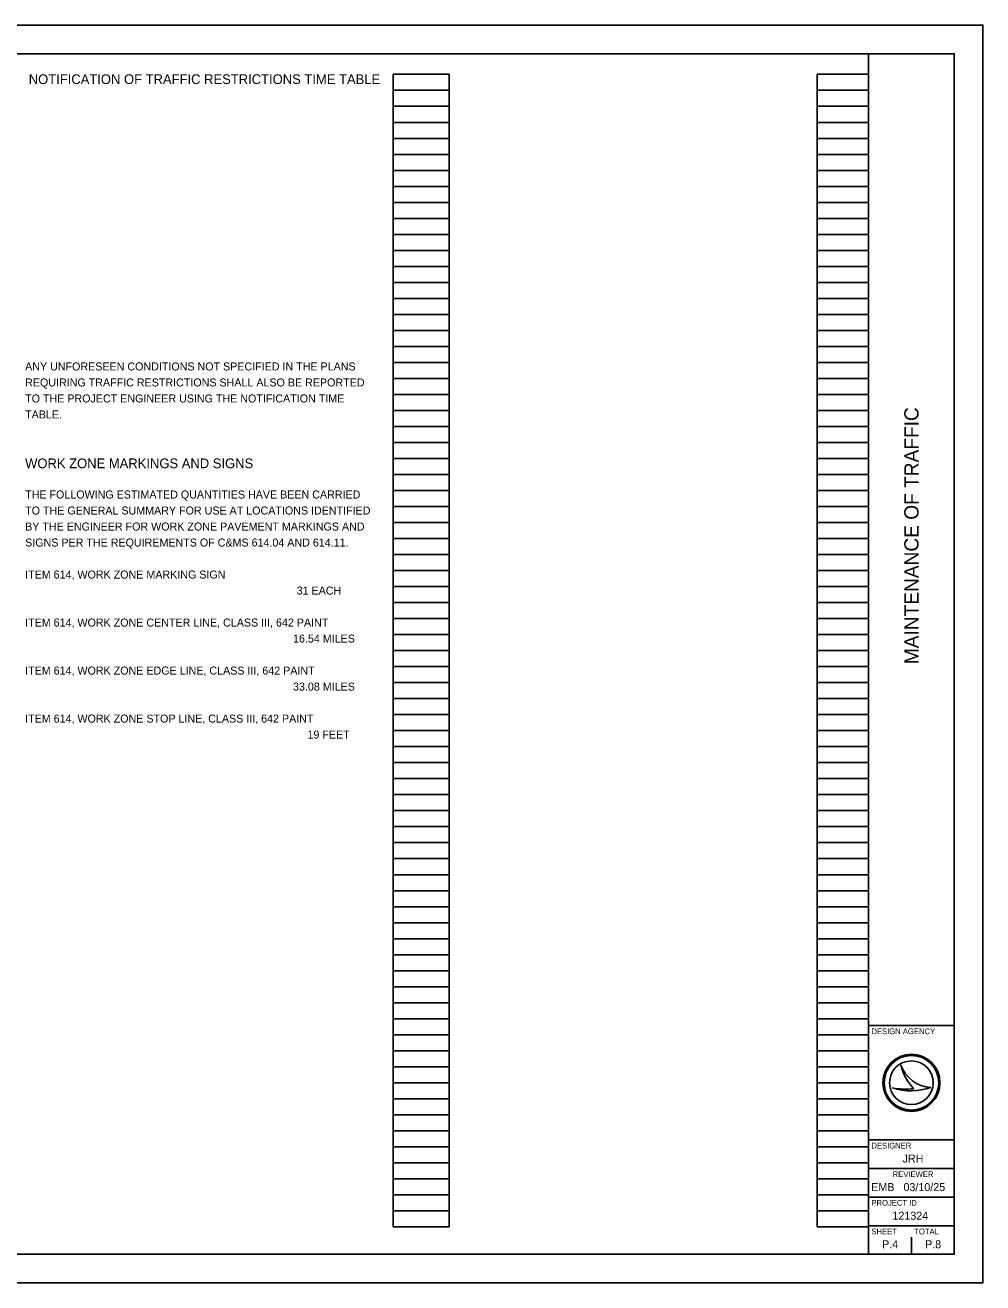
# Model space of a CAD drawing. Extents: x 0 to 34, y 0 to 22.
# Drawn here: x 17.24 to 34, y 0 to 22 of the extents above; entities that cross this region are included whole.
import ezdxf

# ---------------------------------------------------------------- set-up
doc = ezdxf.new("R2010")
doc.units = 0
for name, color, linetype in [('SH_Border', 7, 'Continuous'), ('SH_Cut_Line', 7, 'Continuous'), ('SH_Data', 7, 'Continuous'), ('SH_Text', 7, 'Continuous')]:
    doc.layers.add(name, color=color, linetype=linetype)

msp = doc.modelspace()

# ---------------------------------------------------------------- linework, layer by layer
at = {"layer": 'SH_Border'}
for p, q in [((32, 0.5), (32, 21.5)), ((32, 4.5), (33.5, 4.5)), ((32, 2.5), (33.5, 2.5)), ((32, 2), (33.5, 2)), ((32, 1.5), (33.5, 1.5)), ((32, 1), (33.5, 1))]:
    msp.add_line(p, q, dxfattribs=at)
msp.add_lwpolyline([(1.5, 21.5), (33.5, 21.5), (33.5, 0.5), (1.5, 0.5)], close=True, dxfattribs=at)
at = {"layer": 'SH_Cut_Line'}
msp.add_lwpolyline([(0, 0), (34, 0), (34, 22), (0, 22)], close=True, dxfattribs=at)
at = {"layer": 'SH_Data'}
for p, q in [((23.68, 0.98), (23.68, 21.14)), ((23.68, 21.14), (24.66, 21.14)), ((24.66, 0.98), (24.66, 21.14)), ((31.1, 0.98), (31.1, 21.14)), ((31.1, 21.14), (32, 21.14)), ((32, 0.98), (32, 21.14)), ((23.68, 20.86), (24.66, 20.86)), ((31.1, 20.86), (32, 20.86)), ((23.68, 20.58), (24.66, 20.58)), ((31.1, 20.58), (32, 20.58)), ((23.68, 20.3), (24.66, 20.3)), ((31.1, 20.3), (32, 20.3)), ((23.68, 20.02), (24.66, 20.02)), ((31.1, 20.02), (32, 20.02)), ((23.68, 19.74), (24.66, 19.74)), ((31.1, 19.74), (32, 19.74)), ((23.68, 19.46), (24.66, 19.46)), ((31.1, 19.46), (32, 19.46)), ((23.68, 19.18), (24.66, 19.18)), ((31.1, 19.18), (32, 19.18)), ((23.68, 18.9), (24.66, 18.9)), ((31.1, 18.9), (32, 18.9)), ((23.68, 18.62), (24.66, 18.62)), ((31.1, 18.62), (32, 18.62)), ((23.68, 18.34), (24.66, 18.34)), ((31.1, 18.34), (32, 18.34)), ((23.68, 18.06), (24.66, 18.06)), ((31.1, 18.06), (32, 18.06)), ((23.68, 17.78), (24.66, 17.78)), ((31.1, 17.78), (32, 17.78)), ((23.68, 17.5), (24.66, 17.5)), ((31.1, 17.5), (32, 17.5)), ((23.68, 17.22), (24.66, 17.22)), ((31.1, 17.22), (32, 17.22)), ((23.68, 16.94), (24.66, 16.94)), ((31.1, 16.94), (32, 16.94)), ((23.68, 16.66), (24.66, 16.66)), ((31.1, 16.66), (32, 16.66)), ((23.68, 16.38), (24.66, 16.38)), ((31.1, 16.38), (32, 16.38)), ((23.68, 16.1), (24.66, 16.1)), ((31.1, 16.1), (32, 16.1)), ((23.68, 15.82), (24.66, 15.82)), ((31.1, 15.82), (32, 15.82)), ((23.68, 15.54), (24.66, 15.54)), ((31.1, 15.54), (32, 15.54)), ((23.68, 15.26), (24.66, 15.26)), ((31.1, 15.26), (32, 15.26)), ((23.68, 14.98), (24.66, 14.98)), ((31.1, 14.98), (32, 14.98)), ((23.68, 14.7), (24.66, 14.7)), ((31.1, 14.7), (32, 14.7)), ((23.68, 14.42), (24.66, 14.42)), ((31.1, 14.42), (32, 14.42)), ((23.68, 14.14), (24.66, 14.14)), ((31.1, 14.14), (32, 14.14)), ((23.68, 13.86), (24.66, 13.86)), ((31.1, 13.86), (32, 13.86)), ((23.68, 13.58), (24.66, 13.58)), ((31.1, 13.58), (32, 13.58)), ((23.68, 13.3), (24.66, 13.3)), ((31.1, 13.3), (32, 13.3)), ((23.68, 13.02), (24.66, 13.02)), ((31.1, 13.02), (32, 13.02)), ((23.68, 12.74), (24.66, 12.74)), ((31.1, 12.74), (32, 12.74)), ((23.68, 12.46), (24.66, 12.46)), ((31.1, 12.46), (32, 12.46)), ((23.68, 12.18), (24.66, 12.18)), ((31.1, 12.18), (32, 12.18)), ((23.68, 11.9), (24.66, 11.9)), ((31.1, 11.9), (32, 11.9)), ((23.68, 11.62), (24.66, 11.62)), ((31.1, 11.62), (32, 11.62)), ((23.68, 11.34), (24.66, 11.34)), ((31.1, 11.34), (32, 11.34)), ((23.68, 11.06), (24.66, 11.06)), ((31.1, 11.06), (32, 11.06)), ((23.68, 10.78), (24.66, 10.78)), ((31.1, 10.78), (32, 10.78)), ((23.68, 10.5), (24.66, 10.5)), ((31.1, 10.5), (32, 10.5)), ((23.68, 10.22), (24.66, 10.22)), ((31.1, 10.22), (32, 10.22)), ((23.68, 9.94), (24.66, 9.94)), ((31.1, 9.94), (32, 9.94)), ((23.68, 9.66), (24.66, 9.66)), ((31.1, 9.66), (32, 9.66)), ((23.68, 9.38), (24.66, 9.38)), ((31.1, 9.38), (32, 9.38)), ((23.68, 9.1), (24.66, 9.1)), ((31.1, 9.1), (32, 9.1)), ((23.68, 8.82), (24.66, 8.82)), ((31.1, 8.82), (32, 8.82)), ((23.68, 8.54), (24.66, 8.54)), ((31.1, 8.54), (32, 8.54)), ((23.68, 8.26), (24.66, 8.26)), ((31.1, 8.26), (32, 8.26)), ((23.68, 7.98), (24.66, 7.98)), ((31.1, 7.98), (32, 7.98)), ((23.68, 7.7), (24.66, 7.7)), ((31.1, 7.7), (32, 7.7)), ((23.68, 7.42), (24.66, 7.42)), ((31.1, 7.42), (32, 7.42)), ((23.68, 7.14), (24.66, 7.14)), ((31.1, 7.14), (32, 7.14)), ((23.68, 6.86), (24.66, 6.86)), ((31.1, 6.86), (32, 6.86)), ((23.68, 6.58), (24.66, 6.58)), ((31.1, 6.58), (32, 6.58)), ((23.68, 6.3), (24.66, 6.3)), ((31.1, 6.3), (32, 6.3)), ((23.68, 6.02), (24.66, 6.02)), ((31.1, 6.02), (32, 6.02)), ((23.68, 5.74), (24.66, 5.74)), ((31.1, 5.74), (32, 5.74)), ((23.68, 5.46), (24.66, 5.46)), ((31.1, 5.46), (32, 5.46)), ((23.68, 5.18), (24.66, 5.18)), ((31.1, 5.18), (32, 5.18)), ((23.68, 4.9), (24.66, 4.9)), ((31.1, 4.9), (32, 4.9)), ((23.68, 4.62), (24.66, 4.62)), ((31.1, 4.62), (32, 4.62)), ((23.68, 4.34), (24.66, 4.34)), ((31.1, 4.34), (32, 4.34)), ((23.68, 4.06), (24.66, 4.06)), ((31.1, 4.06), (32, 4.06)), ((23.68, 3.78), (24.66, 3.78)), ((31.1, 3.78), (32, 3.78)), ((32.567, 3.81), (32.567, 3.81)), ((23.68, 3.5), (24.66, 3.5)), ((31.1, 3.5), (32, 3.5)), ((32.417, 3.41), (32.417, 3.41)), ((32.75, 3.5), (32.75, 3.5)), ((33.087, 3.419), (33.087, 3.419)), ((23.68, 3.22), (24.66, 3.22)), ((31.1, 3.22), (32, 3.22)), ((23.68, 2.94), (24.66, 2.94)), ((31.1, 2.94), (32, 2.94)), ((23.68, 2.66), (24.66, 2.66)), ((31.1, 2.66), (32, 2.66)), ((23.68, 2.38), (24.66, 2.38)), ((31.1, 2.38), (32, 2.38)), ((23.68, 2.1), (24.66, 2.1)), ((31.1, 2.1), (32, 2.1)), ((23.68, 1.82), (24.66, 1.82)), ((31.1, 1.82), (32, 1.82)), ((23.68, 1.54), (24.66, 1.54)), ((31.1, 1.54), (32, 1.54)), ((23.68, 1.26), (24.66, 1.26)), ((31.1, 1.26), (32, 1.26)), ((23.68, 0.98), (24.66, 0.98)), ((31.1, 0.98), (32, 0.98)), ((32.375, 0.675), (32.375, 0.675)), ((32.75, 0.5), (32.75, 0.8))]:
    msp.add_line(p, q, dxfattribs=at)
for radius in [0.5, 0.477, 0.477, 0.382]:
    msp.add_circle((32.75, 3.5), radius, dxfattribs=at)
for centre, radius, start, end in [((33.116, 3.998), 0.58, 198.9257, 198.9319), ((33.347, 3.97), 0.796, 191.6379, 191.6421), ((33.116, 3.998), 0.58, 198.9319, 267.1657), ((33.347, 3.97), 0.796, 191.6421, 226.0947), ((32.739, 4.37), 1.013, 251.4576, 290.0832), ((32.648, 4.654), 1.266, 259.4964, 259.4995), ((32.739, 4.37), 1.013, 251.4527, 251.4576), ((32.648, 4.654), 1.266, 259.4995, 276.6672)]:
    msp.add_arc(centre, radius, start, end, dxfattribs=at)

# ---------------------------------------------------------------- texts
msp.add_text('MAINTENANCE OF TRAFFIC', height=0.25, rotation=90, dxfattribs=at).set_placement((32.875, 10.822))
for s, height, p in [('DESIGN AGENCY', 0.1, (32.05, 4.35)), ('DESIGNER', 0.1, (32.05, 2.35)), ('JRH', 0.14, (32.595, 2.105)), ('REVIEWER', 0.1, (32.422, 1.85)), ('EMB', 0.14, (32.047, 1.605)), ('03/10/25', 0.14, (32.611, 1.605)), ('PROJECT ID', 0.1, (32.05, 1.35)), ('121324', 0.14, (32.418, 1.105)), ('SHEET', 0.1, (32.05, 0.85)), ('TOTAL', 0.1, (32.8, 0.85)), ('P.4', 0.14, (32.237, 0.605)), ('P.8', 0.14, (32.989, 0.605))]:
    msp.add_text(s, height=height, dxfattribs=at).set_placement(p)
at = {"layer": 'SH_Text'}
for s, height, p in [(' NOTIFICATION OF TRAFFIC RESTRICTIONS TIME TABLE', 0.17, (17.24, 20.97)), ('ANY UNFORESEEN CONDITIONS NOT SPECIFIED IN THE PLANS', 0.14, (17.24, 15.96)), ('REQUIRING TRAFFIC RESTRICTIONS SHALL ALSO BE REPORTED', 0.14, (17.24, 15.68)), ('TO THE PROJECT ENGINEER USING THE NOTIFICATION TIME', 0.14, (17.24, 15.4)), ('TABLE.', 0.14, (17.24, 15.12)), ('WORK ZONE MARKINGS AND SIGNS', 0.17, (17.24, 14.25)), ('THE FOLLOWING ESTIMATED QUANTITIES HAVE BEEN CARRIED', 0.14, (17.24, 13.72)), ('TO THE GENERAL SUMMARY FOR USE AT LOCATIONS IDENTIFIED', 0.14, (17.24, 13.44)), ('BY THE ENGINEER FOR WORK ZONE PAVEMENT MARKINGS AND', 0.14, (17.24, 13.16)), ('SIGNS PER THE REQUIREMENTS OF C&MS 614.04 AND 614.11.', 0.14, (17.24, 12.88)), ('ITEM 614, WORK ZONE MARKING SIGN', 0.14, (17.24, 12.32)), ('                31 EACH', 0.14, (21.16, 12.04)), ('ITEM 614, WORK ZONE CENTER LINE, CLASS III, 642 PAINT', 0.14, (17.24, 11.48)), ('    16.54 MILES', 0.14, (21.72, 11.2)), ('ITEM 614, WORK ZONE EDGE LINE, CLASS III, 642 PAINT', 0.14, (17.24, 10.64)), ('    33.08 MILES', 0.14, (21.72, 10.36)), ('ITEM 614, WORK ZONE STOP LINE, CLASS III, 642 PAINT', 0.14, (17.24, 9.8)), ('                                                                                               19 FEET', 0.14, (17.24, 9.52))]:
    msp.add_text(s, height=height, dxfattribs=at).set_placement(p)

doc.saveas('drawing.dxf')
